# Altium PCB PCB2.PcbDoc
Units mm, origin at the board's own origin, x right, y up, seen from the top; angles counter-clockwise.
Board outline 100 x 70 mm, 2 copper layers (Top Layer, Bottom Layer), stack 1.173 mm thick; 45 components, 41 nets, 191 pads, 0 vias.
Unrouted connection lines stored in the file: 94.
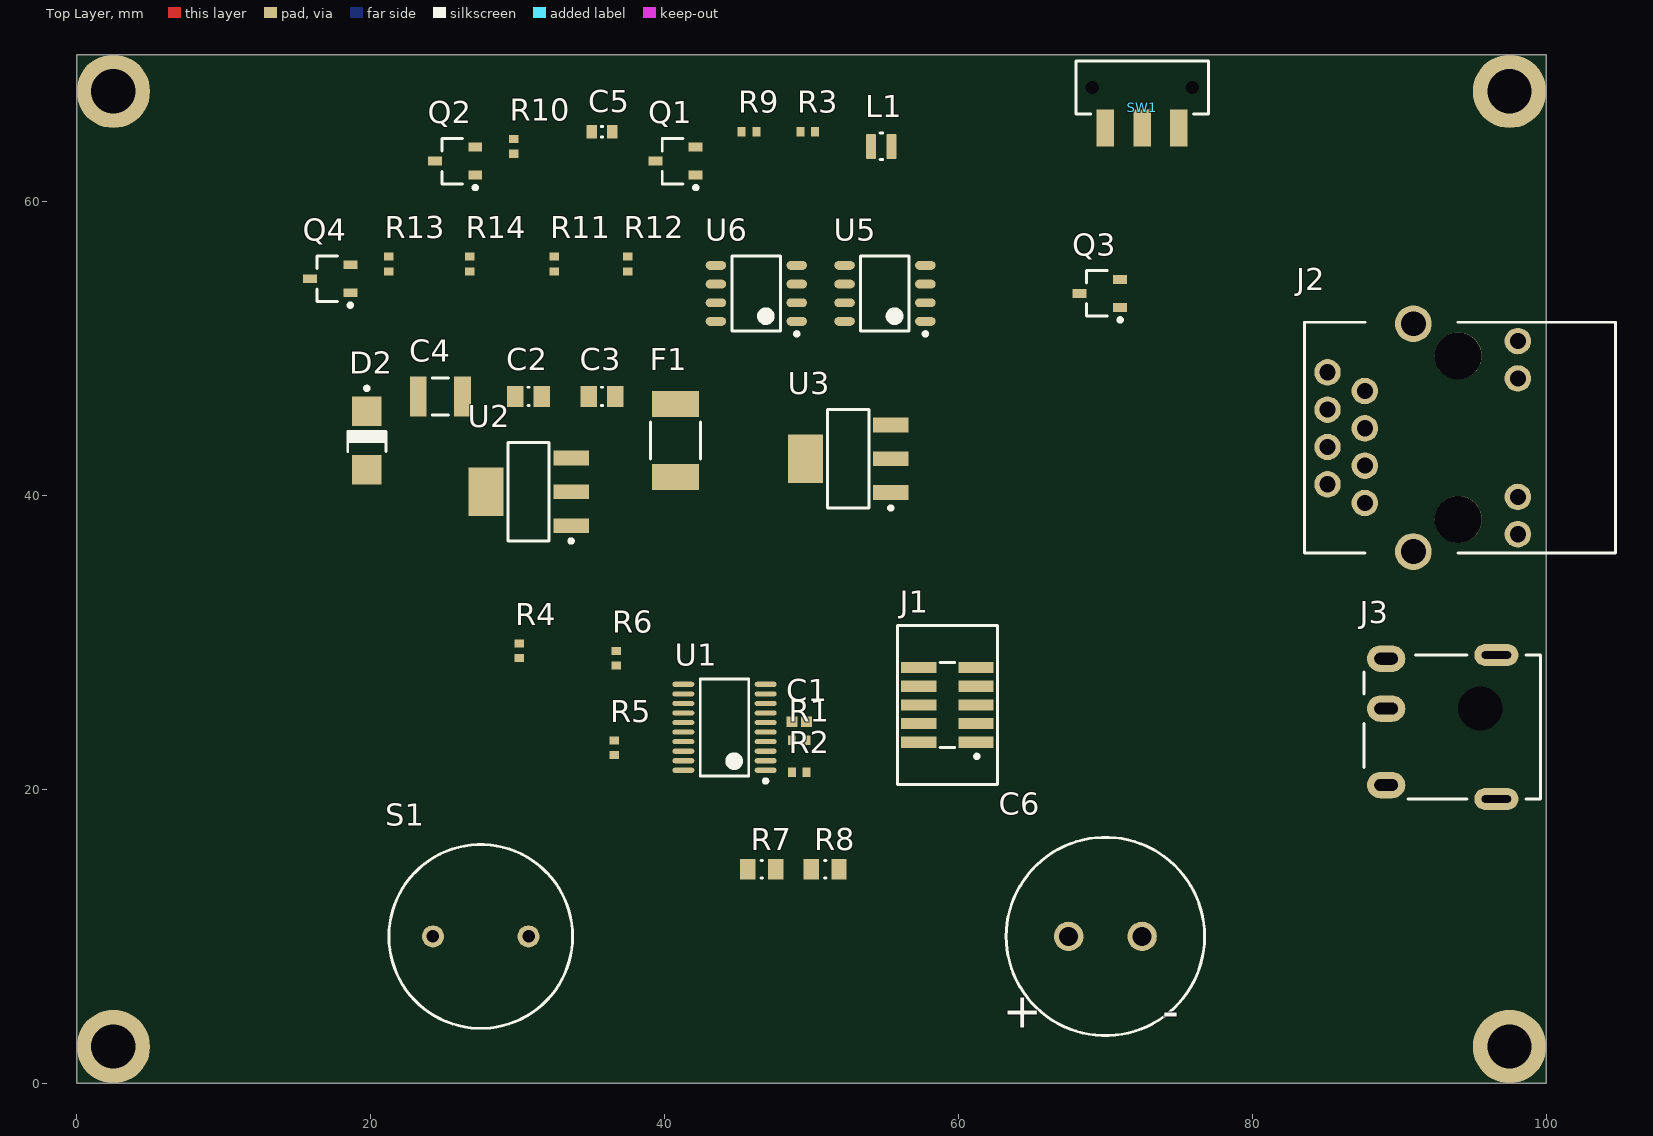
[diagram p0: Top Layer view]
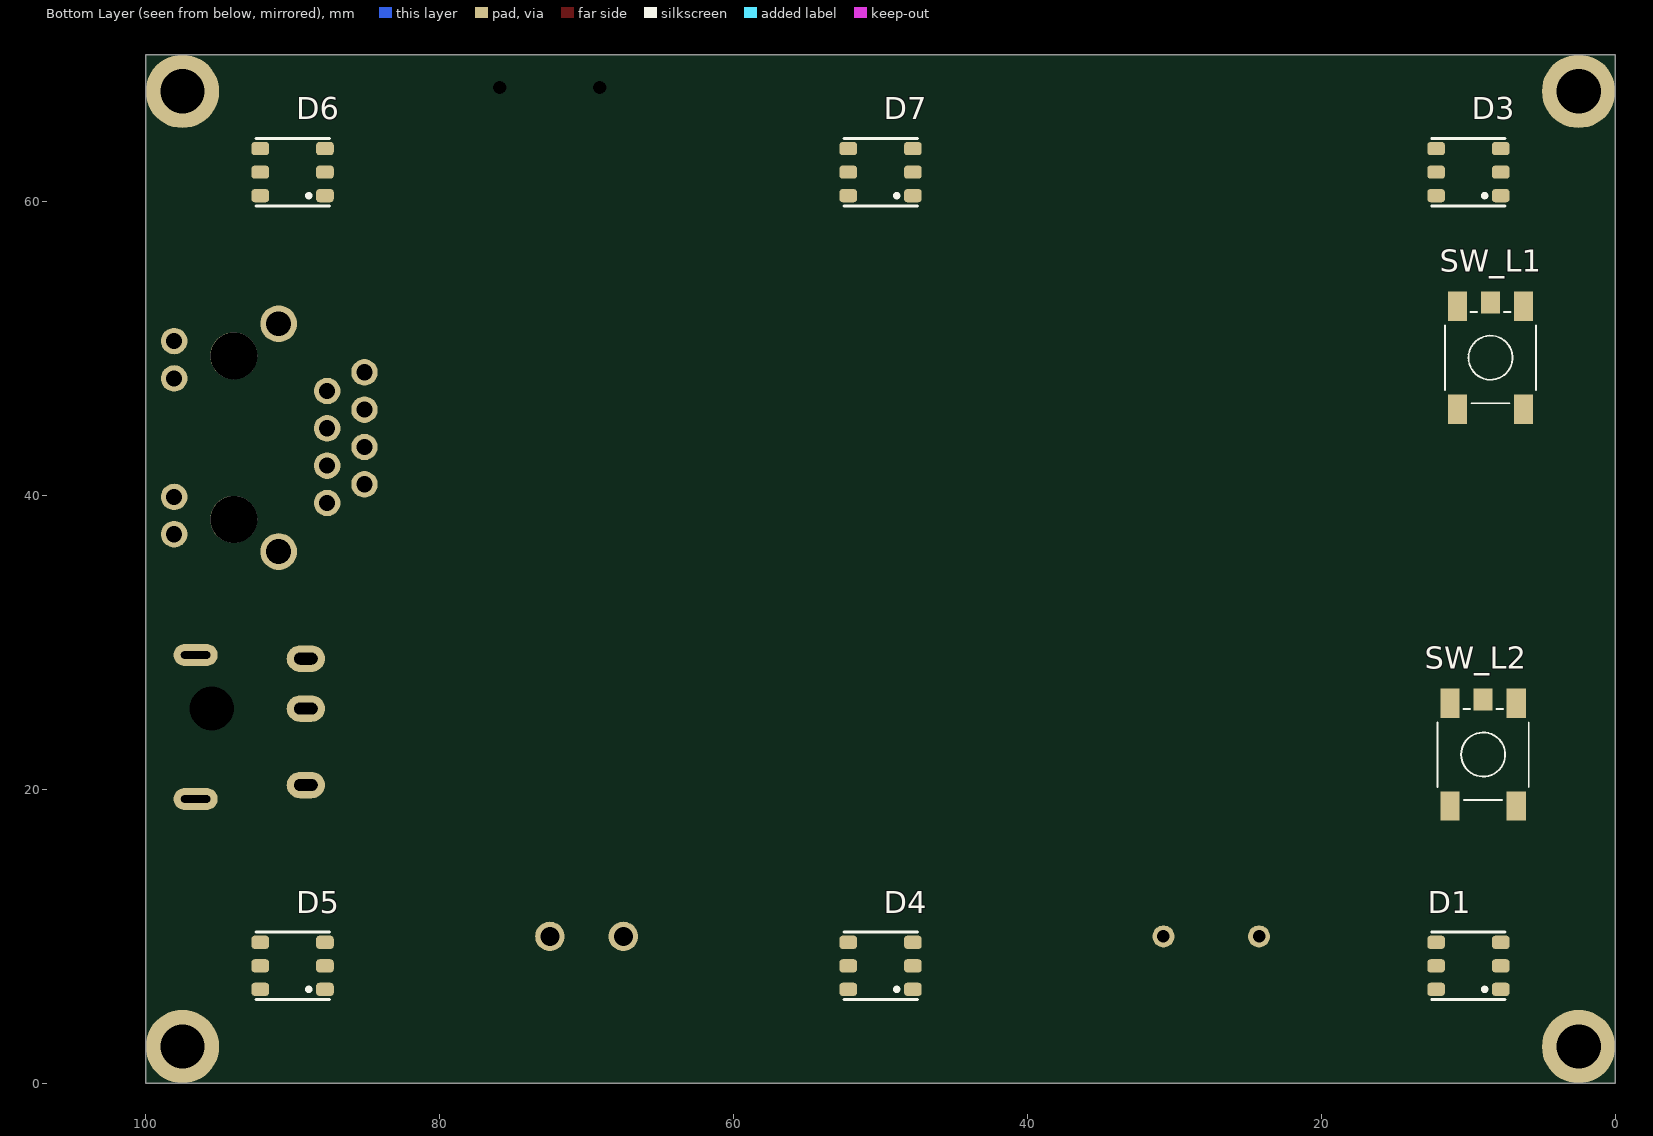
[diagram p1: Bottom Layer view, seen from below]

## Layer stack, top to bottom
Top Solder: solder mask 0.0127, Solder Resist, Dk 3.8
Top Layer: signal copper 0.0356
Dielectric 1: dielectric 1.102, FR-4, Dk 4.8
Bottom Layer: signal copper 0.0356
Bottom Solder: solder mask 0.0127, Solder Resist, Dk 3.8

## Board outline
0,0 0,70 100,70 100,0

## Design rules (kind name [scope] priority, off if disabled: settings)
Clearance [All] p1: gap=0.254 ignorepadtopadclearanceinfootprint=FALSE except(0: Arc-Hole Track-Hole SMDPad-Hole THPad-Hole Via-Hole Fill-Hole Poly-Hole Region-Hole Text-Hole)
PolygonConnect [All] p1: connectstyle=Relief reliefconductorwidth=0.254 reliefentries=4 polygonreliefangle="90 Angle" airgapwidth=0.254
RoomDefinition power [InComponentClass('power')] p1: confinementstyle=ConfineIn formatcopy=TRUE lockcomponents=FALSE outline 17.75,38.74 62.75,38.74 62.75,51.74 17.75,51.74
RoutingVias [All] p1: holewidth=0.711 width=1.27 viastyle="Through Hole" minholewidth=0.711 minwidth=1.27 maxholewidth=0.711 maxwidth=1.27
SolderMaskExpansion [All] p1: expansion=0.102 istentingtop=FALSE
Width [All] p1: maxlimit=0.254 minlimit=0.254 preferedwidth=0.254
30 further rules are at their usual default settings.

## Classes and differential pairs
component class power: C2 C3 C4 C6 D2 F1 J3 SW1 U2 U3
component class Sheet2: C1 C5 D1 D3 D4 D5 D6 D7 J1 J2 L1 Q1 Q2 Q3 Q4 R1 R2 R3 R4 R5 R6 R7 R8 R9 R10 R11 R12 R13 R14 S1 SW_L1 SW_L2 U1 U5 U6

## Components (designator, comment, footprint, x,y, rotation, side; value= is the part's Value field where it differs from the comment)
C1 "GRM155R71C104KA88D" CAPC1005X55X25ML05T10 49.164,24.61 r180 top
C2 "CAP 10uF 10V 0805(2012)" CAPC0805(2012)145_N 30.75,46.74 r180 top value=10uF
C3 "CAP 10uF 10V 0805(2012)" CAPC0805(2012)145_N 35.75,46.74 r180 top value=10uF
C4 "CAP 10uF 50V 1210(3225)" CAPC1210(3225)190_N 24.75,46.74 r180 top value=10uF
C5 "CAP 4.7uF 10V 0603(1608)" CAPC0603(1608)55_L 35.75,64.75 r180 top value=4.7uF
C6 "SC EB 5R5 474 M" "SC EB 5R5 474 M" 70,10 r0 top
D1 "RBG5050" 5050RGB 10,8 r0 bottom
D2 "MURA110T3G" ONSC-SMA-2-403D-02_V 19.75,43.74 r270 top
D3 "RBG5050" 5050RGB 10,62 r0 bottom
D4 "RBG5050" 5050RGB 50,8 r0 bottom
D5 "RBG5050" 5050RGB 90,8 r0 bottom
D6 "RBG5050" 5050RGB 90,62 r0 bottom
D7 "RBG5050" 5050RGB 50,62 r0 bottom
F1 "mSMD110-33V" SEAANDLAND_1812 40.75,43.74 r270 top
J1 "ARM Cortex JTAG" "1.27mm 2x5 SMD Header" 59.25,25.75 r90 top
J2 "RJ45_59_8P8C_LED" RJ45_59_8P8C_LED 94,43.935 r90 top
J3 "DC-044A-2.5A-2.0" DC-044A-2.5A-2.0 99.6,25.5 r270 top
L1 "FNR201610S2R2MT" FNR201610S 54.75,63.75 r180 top
Q1 "AO3418" SOT95P280X125-3N 40.75,62.75 r180 top
Q2 "AO3418" SOT95P280X125-3N 25.75,62.75 r180 top
Q3 "AO3418" SOT95P280X125-3N 69.625,53.75 r180 top
Q4 "AO3418" SOT95P280X125-3N 17.25,54.75 r180 top
R1 "10K 5% 0402(1005)" RESC0402(1005)_N 49.164,23.34 r180 top value="10000.00 Ohm"
R2 "10K 5% 0402(1005)" RESC0402(1005)_N 49.164,21.181 r0 top value="10000.00 Ohm"
R3 "1K 5%" RESC0402(1005)_N 49.75,64.75 r180 top value="10000.00 Ohm"
R4 "TBD" RESC0402(1005)_N 30.114,29.436 r270 top value="10000.00 Ohm"
R5 "TBD" RESC0402(1005)_N 36.591,22.832 r270 top value="10000.00 Ohm"
R6 "TBD" RESC0402(1005)_N 36.718,28.928 r270 top value="10000.00 Ohm"
R7 "120R 5% 0805(2012)" RESC0805(2012)_N 46.608,14.572 r180 top value="120.00 Ohm"
R8 "120R 5% 0805(2012)" RESC0805(2012)_N 50.926,14.572 r180 top value="120.00 Ohm"
R9 "TBD" RESC0402(1005)_N 45.75,64.75 r180 top value="10000.00 Ohm"
R10 "TBD" RESC0402(1005)_N 29.75,63.75 r270 top value="10000.00 Ohm"
R11 "TBD" RESC0402(1005)_N 32.5,55.75 r270 top value="10000.00 Ohm"
R12 "TBD" RESC0402(1005)_N 37.5,55.75 r270 top value="10000.00 Ohm"
R13 "TBD" RESC0402(1005)_N 21.25,55.75 r270 top value="10000.00 Ohm"
R14 "TBD" RESC0402(1005)_N 26.75,55.75 r270 top value="10000.00 Ohm"
S1 "SFN-1255-0540-35P6.5" SFN-1255-0540-35P6.5 27.5,10 r180 top
SW1 "JS102011SAQN" CKCP-JS102011SAQN-3_V 72.5,66.375 r180 top
SW_L1 "431481031816" 431481031816 8.5,49.5 r270 bottom
SW_L2 "431481031816" 431481031816 9,22.5 r270 bottom
U1 "STM32F030F4P6" STM-TSSOP20_L 44.084,24.229 r180 top
U2 "LD1117S33CTR" SOT-223_N 30.75,40.25 r180 top
U3 "LD1117S33CTR" SOT-223_N 52.5,42.5 r180 top
U5 "AZRS3072" SOIC127P600X175-8N 55,53.75 r180 top
U6 "AZRS3072" SOIC127P600X175-8N 46.25,53.75 r180 top

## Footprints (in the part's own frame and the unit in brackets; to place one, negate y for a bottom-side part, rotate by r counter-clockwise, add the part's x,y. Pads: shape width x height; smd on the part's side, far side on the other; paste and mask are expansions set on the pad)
"1.27mm 2x5 SMD Header" [mm]
  rect 0.76x2.4 smd: 1(-2.54,-1.95) 2(-2.54,1.95) 3(-1.27,-1.95) 4(-1.27,1.95) 5(0,-1.95) 6(0,1.95) 7(1.27,-1.95) 8(1.27,1.95) 9(2.54,-1.95) 10(2.54,1.95)
  silkscreen extent -5.4,-3.4 5.4,3.4, body extent -3.15,-2.75 3.2,2.75, height 4.5
5050RGB [mm]
  rrect50% 1.2x0.9 smd: 1(-2.2,1.6) 2(-2.2,0) 3(-2.2,-1.6) 4(2.2,-1.6) 5(2.2,0) 6(2.2,1.6)
  silkscreen extent -2.5,-2.3 2.5,2.3, body extent -2.7,-2.5 2.7,2.5, height 1.6
431481031816 [mm] "6*6mm vertical type, SMD, height 3.1mm, black actuator, 160gf, Grounded Terminal, T&R"
  rect 2x1.3 smd: 1(3.625,-2.25) 2(-3.375,-2.25) 3(3.625,2.25) 4(-3.375,2.25)
  rect 1.5x1.3 smd: 5(-3.625,0)
  silkscreen extent -2.98,-3.1 3.22,3.1, body extent -3.88,-3.1 4.12,3.1, height 3.09
CAPC0603(1608)55_L [mm] "Chip Capacitor, Body 1.6x0.8mm, Height 0.55mm, IPC High Density"
  rect 0.7x0.9 smd: 1(-0.7,0) 2(0.7,0)
  silkscreen extent -0.05,-0.35 0.05,0.35, body extent -0.87,-0.47 0.88,0.48, height 0.55
CAPC0805(2012)145_N [mm] "Chip Capacitor, Body 2.0x1.2mm, Height 1.45mm, IPC Medium Density"
  rect 1.15x1.45 smd: 1(-0.9,0) 2(0.9,0)
  silkscreen extent -0.05,-0.62 0.05,0.63, body extent -1.1,-0.72 1.1,0.73, height 1.45
CAPC1005X55X25ML05T10 [mm] "Chip Capacitor, 2-Leads, Body 1.00x0.50mm, IPC Low Density"
  rect 0.76x0.72 smd: 1(-0.49,0) 2(0.49,0)
  body extent -0.53,-0.28 0.53,0.27, height 0.55
CAPC1210(3225)190_N [mm] "Chip Capacitor, Body 3.2x2.5mm, Height 1.9mm, IPC Medium Density"
  rect 1.15x2.7 smd: 1(-1.5,0) 2(1.5,0)
  silkscreen extent -0.55,-1.25 0.55,1.25, body extent -1.7,-1.35 1.7,1.35, height 1.9
CKCP-JS102011SAQN-3_V [mm] "SMD, 3-Leads, Body 9x3.6mm, Pitch 2.5mm"
  rect 1.2x2.5 smd: 1(-2.5,1.375) 2(0,1.375) 3(2.5,1.375)
  round 0.6 hole 0.9 unplated: MH1(-3.4,-1.375) MH2(3.4,-1.375)
  silkscreen extent -4.5,-3.17 4.5,0.43, body extent -4.5,-5.18 4.5,2.37, height 3.52
DC-044A-2.5A-2.0 [mm] "DC Jack, 6mm OD, 2mm ID"
  rrect100% 1.8x2.6 hole 0.8 slot 1.6 at 90 deg: 1(-3.4,-10.5) 2(5.2,-10.5) 3(0,-10.5)
  rrect100% 1.5x3 hole 0.5 slot 2 at 90 deg: 4(-3.65,-3) 5(6.15,-3)
  rrect100% 2x2 hole 3 unplated: MNT(0,-4.1)
  silkscreen extent -3.65,-12 6.15,0, body extent -3.75,-11.75 6.35,0, height 7.3
FNR201610S [mm] "Wire Wound SMD Power Inductors 2.0×1.6×1.0"
  rrect25% 0.7x1.7 smd paste+0: 1(-0.7,0) 2(0.7,0)
  silkscreen extent -0.1,-0.9 0.1,0.9, body extent -1,-0.8 1,0.8, height 0.95
ONSC-SMA-2-403D-02_V [mm] "Molded, 2-Leads, Body 4.57x2.92mm"
  rect 2x2 smd: 1(-2,0) 2(2,0)
  silkscreen extent -3.67,-1.3 0.74,1.3, body extent -2.16,-1.3 2.16,1.3, height 2.2
RESC0402(1005)_N [mm] "Chip Resistor, Body 1.0x0.5mm, IPC Medium Density"
  rect 0.55x0.65 smd: 1(-0.5,0) 2(0.5,0)
  body extent -0.52,-0.27 0.53,0.28, height 0.4
RESC0805(2012)_N [mm] "Chip Resistor, Body 2.0x1.3mm, IPC Medium Density"
  rect 1.05x1.4 smd: 1(-0.95,0) 2(0.95,0)
  silkscreen extent -0.05,-0.6 0.05,0.6, body extent -1.1,-0.67 1.1,0.68, height 0.7
RJ45_59_8P8C_LED [mm] "Generic RJ49 jack with LED and without magnetics"
  round 1.8 hole 1.1: 1(-4.445,6.35) 2(-3.175,8.89) 3(-1.905,6.35) 4(-0.635,8.89) 5(0.635,6.35) 6(1.905,8.89) 7(3.175,6.35) 8(4.445,8.89) 9(-6.57,-4.06) 10(-4.03,-4.06) 11(4.03,-4.06) 12(6.57,-4.06)
  round 3.2 hole 3.2 unplated: POS1(-5.565,0) POS2(5.565,0)
  round 2.5 hole 1.7: S1(-7.75,3.05) S2(7.75,3.05)
  silkscreen extent -7.85,-10.7 7.85,10.46, body extent -7.85,-10.58 7.85,10.58, height 13.45
"SC EB 5R5 474 M" [mm] "Wincap 5.5V, .47F supercap"
  round 2 hole 1.3: 1(-2.5,0) 2(2.5,0)
  silkscreen extent -6.75,-6.75 6.75,6.75, body extent -6.73,-6.72 6.73,6.72, height 7
SEAANDLAND_1812 [mm] "Surface Mount Fuses 1812"
  rrect0% 1.78x3.2 smd paste+0: 1(-2.49,0) 2(2.49,0)
  silkscreen extent -1.25,-1.71 1.25,1.71, body extent 0,-0.25 0.2,0, height 2
SFN-1255-0540-35P6.5 [mm] "Piezo Buzzer, 4KHz"
  round 1.5 hole 0.85 unplated: 1(-3.25,0) 2(3.25,0)
  silkscreen extent -6.25,-6.25 6.25,6.25, body extent -6.25,-6.25 6.25,6.25, height 5.5
SOIC127P600X175-8N [mm] "SOIC, 8-Leads, Body 4.90x3.90mm, Pitch 1.27mm, IPC Medium Density"
  oval 1.4x0.6 smd: 1(-2.75,1.905) 2(-2.75,0.635) 3(-2.75,-0.635) 4(-2.75,-1.905) 5(2.75,-1.905) 6(2.75,-0.635) 7(2.75,0.635) 8(2.75,1.905)
  silkscreen extent -2.88,-2.55 1.65,2.88, body extent -3,-2.55 3,2.55, height 1.75
SOT95P280X125-3N [mm] "SOT23, 3-Leads, Body 2.95x2.80mm, Pitch 0.95mm, IPC Medium Density"
  rect 0.95x0.6 smd: 1(-1.375,0.95) 2(-1.375,-0.95) 3(1.375,0)
  silkscreen extent -1.5,-1.55 0.9,1.92, body extent -1.5,-1.55 1.5,1.55, height 1.25
SOT-223_N [mm] "SOT223, 4-Leads, Body 6.5x3.5mm, Pitch 2.3mm, Lead Span 7mm, IPC Medium Density"
  rect 2.4x1 smd: 1(-2.9,2.3) 2(-2.9,0) 3(-2.9,-2.3)
  rect 2.4x3.3 smd: 4(2.9,0)
  silkscreen extent -3.03,-3.35 1.4,3.47, body extent -1.85,-3.35 1.85,3.35, height 1.8
STM-TSSOP20_L [mm] "SOP, 20-Leads, Body 6.6x4.5mm, Pitch 0.65mm, IPC High Density"
  oval 1.5x0.35 smd: 1(-2.8,2.925) 2(-2.8,2.275) 3(-2.8,1.625) 4(-2.8,0.975) 5(-2.8,0.325) 6(-2.8,-0.325) 7(-2.8,-0.975) 8(-2.8,-1.625) 9(-2.8,-2.275) 10(-2.8,-2.925) 11(2.8,-2.925) 12(2.8,-2.275) 13(2.8,-1.625) 14(2.8,-0.975) 15(2.8,-0.325) 16(2.8,0.325) 17(2.8,0.975) 18(2.8,1.625) 19(2.8,2.275) 20(2.8,2.925)
  silkscreen extent -2.93,-3.3 1.65,3.77, body extent -2.25,-3.3 2.25,3.3, height 1.2

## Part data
C1: library part CMP-2100-03641-1, "Chip Capacitor, 0.1 uF, +/- 10%, 16 V, -55 to 125 degC, 0402 (1005 Metric), RoHS, Tape and Reel", Capacitance=100nF, Case Code (Imperial)=0402, Case Code (Metric)=1005, Dielectric=X7R, Dielectric Material=Ceramic, Insulation Resistance=10GR, Manufacturer=Murata, Max Operating Temperature=125degC, Min Operating Temperature=-55degC, Package Description="2-Pin Surface Mount Device, Body 1 x 0.5 mm", Package Quantity=1, Tolerance=10%, Voltage=16V
C2 C3: library part CMP-1036-04922-1, "CAP 10uF 10V ±10% 0805 (2012 Metric) Thickness 1.45mm SMD", Case-EIA=0805, Case-Metric=2012, Rated Voltage="10 V", Tolerance=Â±10%
C4: library part CMP-1038-02238-1, "CAP 10uF 50V -20% to +80% 1210 (3225 Metric) Thickness 1.9mm SMD", Case-EIA=1210, Case-Metric=3225, Rated Voltage="50 V", Tolerance="-20% to +80%"
C5: library part CMP-1035-02784-1, "CAP 4.7uF 10V ±10% 0603 (1608 Metric) Thickness 0.55mm SMD", Case-EIA=0603, Case-Metric=1608, Rated Voltage="10 V", Tolerance=Â±10%
C6: "Wincap .47F, 5.5V, thru-hole supercap", Manufacturer=Wincap
D1 D3 D4 D5 D6 D7: "Generic RGB LED in 5050 package. Note that several variants exist, so check the pinout!", Manufacturer=Unknown/Generic
D2: library part CMP-0902-00293-1, "Surface Mount Ultrafast Power Rectifier, 2-Pin SMA, Pb-Free, Tape and Reel", Manufacturer="On Semiconductor"
F1: "Surface Mount Fuses 33V 100A 1.1A 2.2A 1812 RoHS", Manufacturer="Sea & Land Electronic Corp"
J1: "Arm Cortex 10-pin JTAG connector", Manufacturer=Unknown/Generic, PartNumber=unknown/Generic
J2: "Generic RJ49 jack with LED and without magnetics", Manufacturer=Unknown/Generic
J3: "DC Jack, 6mm OD, 2mm ID", Manufacturer=XKB
L1: "Wire Wound SMD Power Inductors 2.0×1.6×1.0 2.2uH"
Q1 Q2 Q3 Q4: "30V N-Channel MOSFET", Manufacturer="Alpha & Omega"
R1 R2 R3 R4 R5 R6 R9 R10 R11 R12 R13 R14: library part CMP-1011-00098-1, "10K 0.063W 5% 0402 (1005 Metric)  SMD", Case-EIA=0402, Case-Metric=1005, Power="0.063 W", Tolerance="5 %"
R7 R8: library part CMP-1013-00052-1, "120R 0.125W 5% 0805 (2012 Metric)  SMD", Case-EIA=0805, Case-Metric=2012, Power="0.125 W", Tolerance="5 %"
S1: "Piezo Buzzer, 4KHz", Manufacturer=S&S
SW1: library part CMP-2000-06501-1, "Sub-Miniature Slide Switch, SPDT, -40 to 85 degC, 3-Pin SMD, RoHS, Tape and Reel", Actuator Color=Black, Contact Rating @ Voltage=0.3@6VDCA, Dielectric Strength=500VAC, Manufacturer="C&K Components", Maximum AC Voltage Rating=N/A, Maximum Contact Resistance=70mOhm, Maximum DC Voltage Rating=6V, Minimum Insulation Resistance=100MOhm, Operating Temperature=-40to85C, Package Description="3-Pin Surface Mount Device, Body 9 x 3.6 mm, Height 3.5 mm", Package Reference=SMT
SW_L1 SW_L2: library part CMP-1457-00011-1, "WS-TASV SMD Tact Switch 6X6 mm with ground terminal", Manufacturer="Wuerth Elektronik"
U1: library part CMP-0304-00039-2, "ARM Cortex-M0 32-bit MCU, 16 KB Flash, 4 KB Internal RAM, 15 I/Os, 20-pin TSSOP, -40 to 85 degC, Tube", I/Os (High Current)=15, Operating Frequency(F) (Processor speed) (MHz)=48, Supply Voltage(Vcc) min (V)=2.4
U2 U3: library part CMP-0244-00307-1, "Fixed Low Drop Positive Voltage Regulator, 3.3V, 4-Pin SOT-223, Tape and Reel"
U5 U6: "ESD-Protected, Slew-Rate-Limited, True Fail-Safe 3.3V RS485 Transceiver IC", Manufacturer="Amazing Microelectronic Corp."

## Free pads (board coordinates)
  round 5 hole 3 unplated: MP1(2.5,2.5) MP2(2.5,67.5) MP3(97.5,67.5) MP4(97.5,2.5)

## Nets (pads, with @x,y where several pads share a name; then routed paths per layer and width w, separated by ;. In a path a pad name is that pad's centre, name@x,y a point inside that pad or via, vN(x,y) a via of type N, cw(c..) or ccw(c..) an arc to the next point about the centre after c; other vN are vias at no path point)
3.3V: C3.2 C6.1 U3.2 U3.4
9V: C2.2 U2.2 U2.4 U3.3
+3.3V: C1.2 D1.4 D1.5 D1.6 J1.1 L1.1 R1.1 U1.5 U1.16 U6.2 U6.3 U6.8
+12V: F1.1 J3.1
\R\S\T: J1.10 R1.2 U1.4
BOOT0: R2.1 U1.1
BUT_CAL: SW_L1.1 SW_L1.2
BUT_EXTRA: SW_L2.1 SW_L2.2 U1.8
GND: C1.1 C2.1 C3.1 C4.1 C5.1 C6.2 D2.2 J1.3 J1.5 J1.9 J2.7 J2.8 J2.S1 J2.S2 J3.2 J3.3 J3.4 J3.5 Q1.2 Q2.2 Q3.2 Q4.2 R2.2 R10.1 SW_L1.3 SW_L1.4 SW_L2.3 SW_L2.4 U1.15 U2.1 U3.1 U5.2 U5.3 U5.5 U6.5
LED_B: R6.1 R13.1 U1.7
LED_G: R14.1 U1.6
LED_R: U1.14
NetC4_2: C4.2 D2.1 F1.2 U2.3
NetD1_1: D1.1 R4.2
NetD1_2: D1.2 R11.2
NetD1_3: D1.3 R12.2
NetL1_2: L1.2
NetQ1_1: Q1.1 R6.2
NetQ1_3: Q1.3 R4.1
NetQ2_3: Q2.3 R3.1 S1.2
NetQ3_1: Q3.1 R13.2
NetQ3_3: Q3.3 R11.1
NetQ4_1: Q4.1 R14.2
NetQ4_3: Q4.3 R12.1
OLED_D/C: U1.3
OLED_RST: U1.2
PIEZO: R5.1 U1.9
SENSOR_RX+: J2.3 R8.1 U6.6
SENSOR_RX-: J2.6 R8.2 U6.7
SENSOR_TX+: J2.1 R7.1 U5.6
SENSOR_TX-: J2.2 R7.2 U5.7
SPI1_MISO: U1.12
SPI1_MOSI: U1.13
SPI1_NSS: U1.10
SPI1_SCK: U1.11
SWCLK: J1.4 U1.20
SWDIO: J1.2 U1.19
USART1_RX: U1.18 U5.1 U5.4
USART1_TX: U1.17 U6.1 U6.4
VFB: R9.1 R10.2
VPIEZO: C5.2 R3.2 R9.2 S1.1
pads on no net: D3.1 D3.2 D3.3 D3.4 D3.5 D3.6 D4.1 D4.2 D4.3 D4.4 D4.5 D4.6 D5.1 D5.2 D5.3 D5.4 D5.5 D5.6 D6.1 D6.2 D6.3 D6.4 D6.5 D6.6 D7.1 D7.2 D7.3 D7.4 D7.5 D7.6 J1.6 J1.7 J1.8 J2.4 J2.5 J2.9 J2.10 J2.11 J2.12 J2.POS1 J2.POS2 J3.MNT Q2.1 R5.2 SW1.1 SW1.2 SW1.3 SW1.MH1 SW1.MH2 SW_L1.5 SW_L2.5 U5.8

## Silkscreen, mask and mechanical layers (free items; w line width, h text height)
Mechanical 1:
  the board outline again, w0.1

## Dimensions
0,70 to 0,0 on Dimensions
0,0 to 100,0 on Dimensions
